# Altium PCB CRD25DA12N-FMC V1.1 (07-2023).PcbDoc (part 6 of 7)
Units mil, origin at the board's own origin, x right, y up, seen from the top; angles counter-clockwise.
Board outline 8000 x 8000 mil, 6 copper layers (Top Layer, Layer 2, Layer 3, Layer 4, Layer 5, Bottom Layer), stack 91 mil thick; 542 components, 315 nets, 1585 pads, 558 vias.
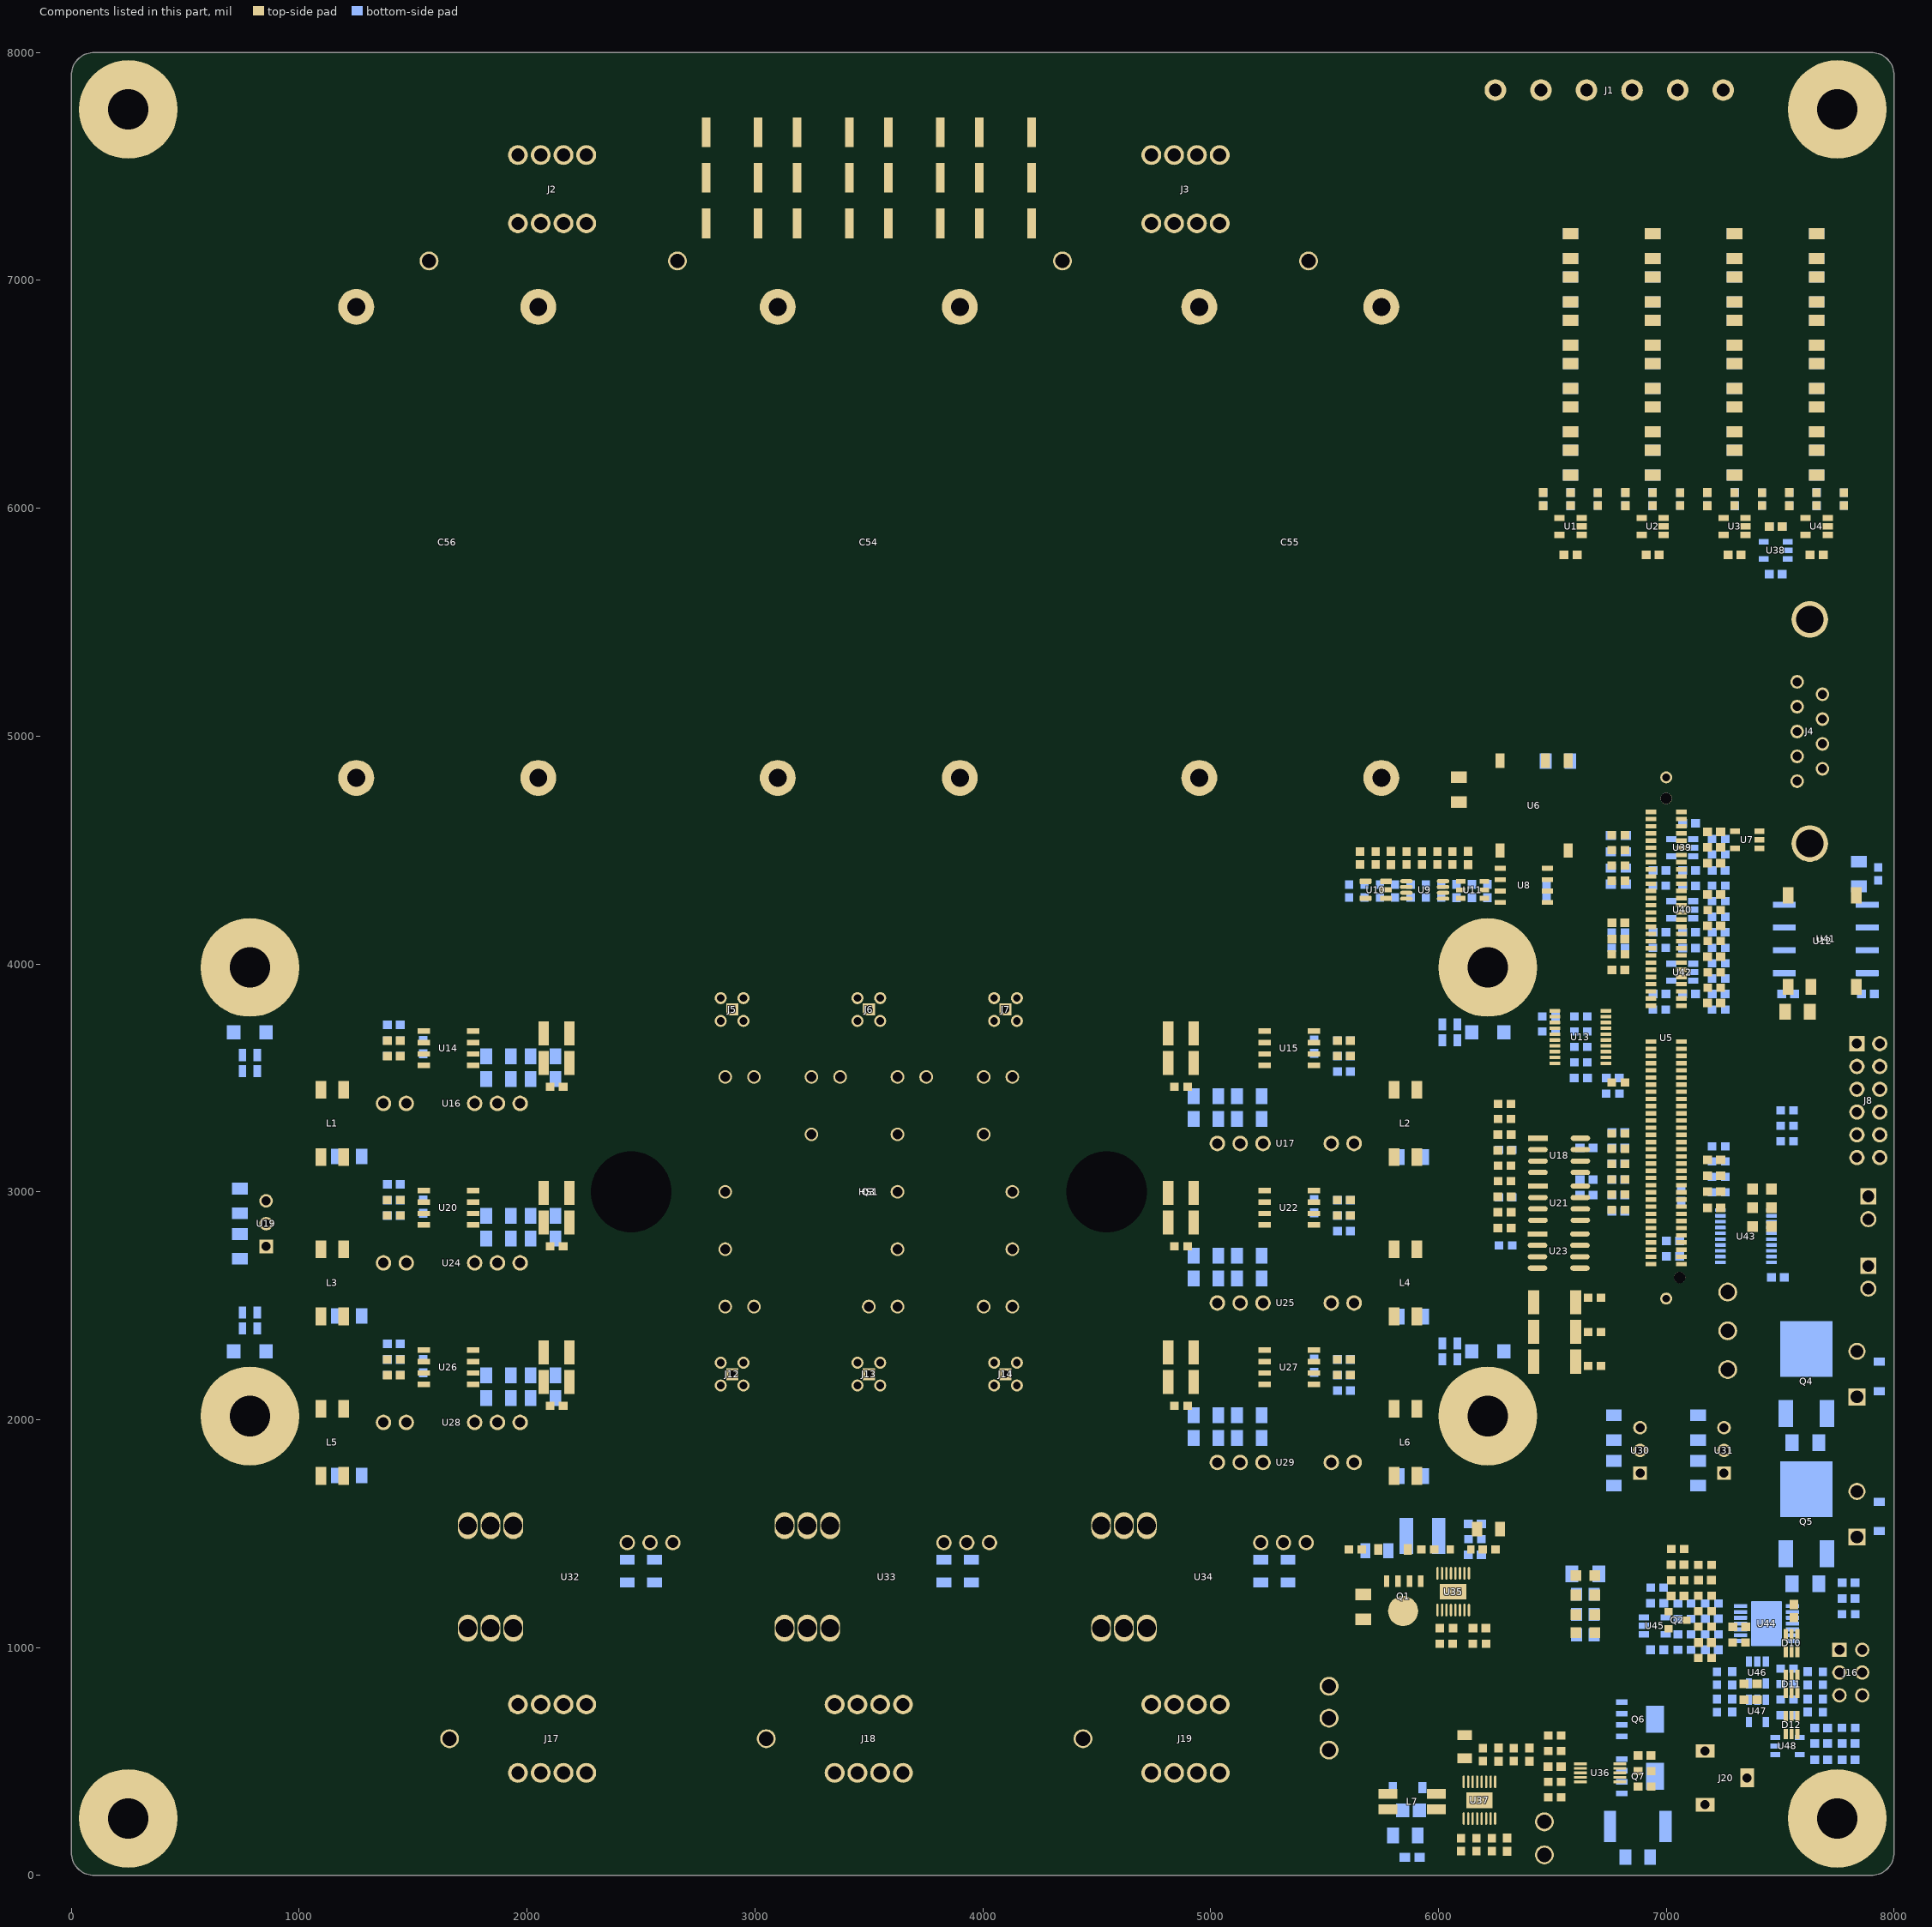
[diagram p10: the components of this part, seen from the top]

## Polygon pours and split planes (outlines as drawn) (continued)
GND on Bottom Layer "GND_L06_P148" (solid, pour order 148): 6825,1941.88 6856.88,1910 6935,1910 6935,1820 6856.88,1820 6825,1788.12 6825,1770 6715,1770 6715,1960 6825,1960
+3.3V on Bottom Layer "+3.3V_L06_P146" (solid, pour order 146): 6803.12,1970 6835,1938.12 6835,1920 6935,1920 6935,2065 6715,2065 6715,1970
GND on Bottom Layer "GND_L06_P145" (solid, pour order 145): 7470,1495 7470,1330 7625,1330 7625,1495
DC- on Layer 5 "DC-_L05_P275" (solid, pour order 275): 1084,3924 2231,3924 2320,3835 2320,2930 4565,2930 5365,3730 5365,4050 5455,4140 5772.5,4137.5 6238,4603 6238,7740 758,7740 758,4250
GND on Layer 5 "GND_L05_P266" (solid, pour order 266): 54 vertices, not listed, extent 2385,50 7950,6175
S4 on Layer 5 "S4_L05_P090" (solid, pour order 90): 4745,2370 5265,2370 5265,1775 4745,1775
S6 on Layer 5 "S6_L05_P091" (solid, pour order 91): 4745,3070 5265,3070 5265,2475 4745,2475
S5 on Layer 5 "S5_L05_P092" (solid, pour order 92): 4745,3770 5265,3770 5265,3175 4745,3175
S1 on Layer 5 "S1_L05_P033" (solid, pour order 33): 1735,3080 2245,3080 2245,2625 1735,2625
S2 on Layer 5 "S2_L05_P341" (solid, pour order 341): 1735,2380 2245,2380 2245,1925 1735,1925
S3 on Layer 5 "S3_L05_P342" (solid, pour order 342): 1735,3780 2245,3780 2245,3325 1735,3325
GND on Layer 5 "GND_L05_P304" (solid, pour order 304): 1395,1850 1470,1850 1470,1925 1575,1925 1575,3725 490,3725 490,1680 1395,1680
U_OUT on Layer 5 "U_OUT_L05_P169" (solid, pour order 169): 1545,1620 1545,340 2455,340 2455,1015 2165,1305 2165,1620
V_OUT on Layer 5 "V_OUT_L05_P168" (solid, pour order 168): 2935,1620 2935,340 3845,340 3845,1015 3555,1305 3555,1620
W_OUT on Layer 5 "W_OUT_L05_P016" (solid, pour order 16): 4325,1620 4325,340 5235,340 5235,1015 4945,1305 4945,1620
GND_ISO on Layer 5 "GND_ISO_L05_P138" (solid, pour order 138): 7725,4445 7725,4365 7810,4365 7810,3845 7950,3845 7950,5595 7540,5595 7540,4445
GND_NTC on Layer 5 "GND_NTC_L05_P263" (solid, pour order 263): 6055,4575 6000,4575 6000,4520 5585,4520 5585,4235 6295,4235 6295,4925 6055,4925
+12V on Top Layer "+12V_L01_P193" (solid, pour order 193): 5880,3795 5880,3940 5805,4015 5580,4015 5205,4390 1545,4390 790,3635 790,3360 960,3360 965,3365 965,3615 1690,4340 5115,4340 5660,3795
G3 on Top Layer "G3_L01_P128" (solid, pour order 128): 18 vertices, not listed, extent 2130,3450 3405,4070
G1 on Top Layer "G1_L01_P061" (solid, pour order 61): 2150,2810 2150,2750 2170,2750 2170,2810 2210,2810 2210,3075 2585,3450 3008.94,3450 3008.94,3560 2520,3560 2130,3170 2130,2810
G2 on Top Layer "G2_L01_P060" (solid, pour order 60): 2150,2110 2150,2050 2170,2050 2170,2110 2210,2110 2210,2210 2445,2445 3045,2445 3045,2555 2400,2555 2195,2350 2130,2350 2130,2110
G6 on Top Layer "G6_L01_P059" (solid, pour order 59): 4775,3060 4775,2800 4530,2555 3955,2555 3955,2445 4615,2445 4870,2700 4870,3060
G5 on Top Layer "G5_L01_P057" (solid, pour order 57): 4735,3665 4789.19,3610.81 4790,3610.81 4790,3440 4870,3440 4870,3754.99 3780.01,3755.01 3705,3680 3705,3515 3755,3465 3795,3465 3795,3600 3860,3665
G4 on Top Layer "G4_L01_P056" (solid, pour order 56): 19 vertices, not listed, extent 3605,1940 4870,2535
+15V on Top Layer "+15V_L01_P235" (solid, pour order 235): 5600,1175 5600,1045 5940,1045 5940,1240 5730,1240 5730,1175
NetD4_2 on Top Layer "NETD4_2_L01_P227" (solid, pour order 227): 5900,1400 5901.49,1400 6015,1400 6015,1120 5950,1120 5950,1360 5830,1360 5830,1475 5900,1475
NetC182_2 on Top Layer "NETC182_2_L01_P224" (solid, pour order 224): 17 vertices, not listed, extent 5840,175 6155,450
GND on Top Layer "GND_L01_P434" (solid, pour order 434): 6530,5000 6530,4825 6638.38,4825 6638.38,5000
+5V_NTC on Top Layer "+5V_NTC_L01_P213" (solid, pour order 213): 6149.83,4525 6200.06,4474.77 6200,4474.77 6200,4445 6295,4445 6295,4760 6055,4760 6055,4675 6055,4525
GND_NTC on Top Layer "GND_NTC_L01_P215" (solid, pour order 215): 6210,4925 6055,4925 6055,4770 6295,4770 6295,4925
GND on Top Layer "GND_L01_P431" (solid, pour order 431): 5715,3305 5715,3555 5850,3555 5850,3305
+12V on Top Layer "+12V_L01_P430" (solid, pour order 430): 5945,3305 5945,3555 5860,3555 5860,3305
NetC105_2 on Top Layer "NETC105_2_L01_P429" (solid, pour order 429): 5850,3065 5480,3065 5480,3295 5850,3295
NetC105_1 on Top Layer "NETC105_1_L01_P428" (solid, pour order 428): 5945,3295 5945,3065 5860,3065 5860,3295
GND on Top Layer "GND_L01_P427" (solid, pour order 427): 5715,2605 5715,2855 5850,2855 5850,2605
+12V on Top Layer "+12V_L01_P426" (solid, pour order 426): 5945,2605 5945,2855 5860,2855 5860,2605
NetC135_2 on Top Layer "NETC135_2_L01_P425" (solid, pour order 425): 5850,2365 5480,2365 5480,2595 5850,2595
NetC135_1 on Top Layer "NETC135_1_L01_P424" (solid, pour order 424): 5945,2595 5945,2365 5860,2365 5860,2595
+12V on Top Layer "+12V_L01_P379" (solid, pour order 379): 1235,1945 1235,2150 1145,2150 1145,1945
NetC157_1 on Top Layer "NETC157_1_L01_P376" (solid, pour order 376): 1195,1935 1195,1937.5 1245,1987.5 1245,2040 1525,2040 1525,1925 1455,1925 1450,1925 1395,1870 1395,1680 1145,1680 1145,1935
NetC156_1 on Top Layer "NETC156_1_L01_P102" (solid, pour order 102): 5945,1895 5945,1665 5860,1665 5860,1895
NetC156_2 on Top Layer "NETC156_2_L01_P103" (solid, pour order 103): 5850,1665 5480,1665 5480,1895 5850,1895
+12V on Top Layer "+12V_L01_P178" (solid, pour order 178): 5945,1905 5945,2155 5860,2155 5860,1905
GND on Top Layer "GND_L01_P184" (solid, pour order 184): 5715,1905 5715,2155 5850,2155 5850,1905
G5L on Top Layer "G5L_L01_P423" (solid, pour order 423): 5265,3595 5265,3620 4900,3620 4900,3510 5100,3510 5185,3595
G5H on Top Layer "G5H_L01_P422" (solid, pour order 422): 5265,3665 5265,3640 4900,3640 4900,3750 5100,3750 5185,3665
+15V_W_HS on Top Layer "-3V_U_LS_TOP" (solid, pour order 421): 5265,3770 5265,3675 5190,3675 5145,3720 5145,3770
-3V_W_HS on Top Layer "+15V_U_LS_TOP" (solid, pour order 420): 5265,3585 5265,3410 5165,3410 5165,3555 5195,3585
G6L on Top Layer "G6L_L01_P419" (solid, pour order 419): 5265,2895 5265,2920 4900,2920 4900,2810 5100,2810 5185,2895
G6H on Top Layer "G6H_L01_P418" (solid, pour order 418): 5265,2965 5265,2940 4900,2940 4900,3050 5100,3050 5185,2965
+15V_W_LS on Top Layer "-3V_U_LS_TOP" (solid, pour order 417): 5265,3070 5265,2975 5190,2975 5145,3020 5145,3070
-3V_W_LS on Top Layer "+15V_U_LS_TOP" (solid, pour order 416): 5265,2885 5265,2710 5165,2710 5165,2855 5195,2885
G4L on Top Layer "G4L_L01_P409" (solid, pour order 409): 5265,2195 5265,2220 4900,2220 4900,2110 5100,2110 5185,2195
G4H on Top Layer "G4H_L01_P408" (solid, pour order 408): 5265,2265 5265,2240 4900,2240 4900,2350 5100,2350 5185,2265
G2H on Top Layer "G2H_L01_P407" (solid, pour order 407): 1735,2195 1735,2220 2100,2220 2100,2110 1900,2110 1815,2195
-3V_U_LS on Top Layer "-3V_U_LS_TOP" (solid, pour order 406): 1735,2370 1735,2275 1810,2275 1855,2320 1855,2370
+15V_U_LS on Top Layer "+15V_U_LS_TOP" (solid, pour order 405): 1860,2035 1915,1980 1915,1925 2015,1925 2015,2095 1900,2095 1810,2185 1735,2185 1735,2035
G2L on Top Layer "G2L_L01_P404" (solid, pour order 404): 1735,2265 1735,2240 2100,2240 2100,2350 1900,2350 1815,2265
G3H on Top Layer "G3H_L01_P403" (solid, pour order 403): 1735,3595 1735,3620 2100,3620 2100,3510 1900,3510 1815,3595
-3V_V_HS on Top Layer "-3V_U_LS_TOP" (solid, pour order 402): 1735,3770 1735,3675 1810,3675 1855,3720 1855,3770
+15V_V_HS on Top Layer "+15V_U_LS_TOP" (solid, pour order 401): 1860,3435 1915,3380 1915,3325 2015,3325 2015,3495 1900,3495 1810,3585 1735,3585 1735,3435
G3L on Top Layer "G3L_L01_P400" (solid, pour order 400): 1735,3665 1735,3640 2100,3640 2100,3752.8 1902.8,3752.79 1815,3665
+12V on Top Layer "+12V_L01_P383" (solid, pour order 383): 1235,3345 1235,3550 1145,3550 1145,3345
GND on Top Layer "GND_L01_P382" (solid, pour order 382): 1135,3345 1135,3550 1045,3550 1045,3345
NetC106_2 on Top Layer "NETC106_2_L01_P381" (solid, pour order 381): 1045,3335 1045,3075 1135,3075 1135,3335
NetC106_1 on Top Layer "NETC106_1_L01_P380" (solid, pour order 380): 1195,3335 1195,3337.5 1245,3387.5 1245,3440 1525,3440 1525,3325 1455,3325 1450,3325 1395,3270 1395,3080 1145,3080 1145,3335
GND on Top Layer "GND_L01_P378" (solid, pour order 378): 1135,1945 1135,2150 1045,2150 1045,1945
NetC157_2 on Top Layer "NETC157_2_L01_P377" (solid, pour order 377): 1045,1935 1045,1675 1135,1675 1135,1935
NetC136_1 on Top Layer "NETC136_1_L01_P077" (solid, pour order 77): 1195,2635 1195,2637.5 1245,2687.5 1245,2740 1525,2740 1525,2625 1455,2625 1450,2625 1395,2570 1395,2380 1145,2380 1145,2635
+12V on Top Layer "+12V_L01_P375" (solid, pour order 375): 1235,2645 1235,2850 1145,2850 1145,2645
NetC136_2 on Top Layer "NETC136_2_L01_P078" (solid, pour order 78): 1045,2635 1045,2375 1135,2375 1135,2635
G1H on Top Layer "G1H_L01_P374" (solid, pour order 374): 1735,2895 1735,2920 2100,2920 2100,2810 1900,2810 1815,2895
+15V_U_HS on Top Layer "+15V_U_LS_TOP" (solid, pour order 330): 1860,2735 1915,2680 1915,2625 2015,2625 2015,2795 1900,2795 1810,2885 1735,2885 1735,2735
NetC159_1 on Top Layer "NETC159_1_L01_P233" (solid, pour order 233): 5630,1475 5630,1385 5685,1330 5795,1330 5795,1265 5935,1265 5935,1345 5820,1345 5820,1475
U_OUT on Top Layer "U_OUT_L01_P278" (solid, pour order 278): 1545,1620 1545,340 2455,340 2455,1015 2165,1305 2165,1620
W_OUT on Top Layer "W_OUT_L01_P276" (solid, pour order 276): 4325,1615 4325,340 5235,340 5235,1015 4945,1305 4945,1615
V_OUT on Top Layer "V_OUT_L01_P277" (solid, pour order 277): 2935,1620 2935,340 3845,340 3845,1015 3555,1305 3555,1620
-3V_U_HS on Top Layer "-3V_U_LS_TOP" (solid, pour order 331): 1735,3070 1735,2975 1810,2975 1855,3020 1855,3070
G1L on Top Layer "G1L_L01_P329" (solid, pour order 329): 1735,2965 1735,2940 2100,2940 2100,3050 1900,3050 1815,2965
-3V_V_LS on Top Layer "+15V_U_LS_TOP" (solid, pour order 124): 5265,2185 5265,2010 5165,2010 5165,2155 5195,2185
+15V_V_LS on Top Layer "-3V_U_LS_TOP" (solid, pour order 125): 5265,2370 5265,2275 5190,2275 5145,2320 5145,2370
+5V_ISO on Top Layer "+5V_ISO_L01_P291" (solid, pour order 291): 7795,4405 7795,4250 7920,4250 7920,4405
GND_ISO on Top Layer "GND_ISO_L01_P289" (solid, pour order 289): 7795,3950 7795,3845 7940,3845 7940,3950
GND on Top Layer "GND_L01_P284" (solid, pour order 284): 7575,3950 7575,3740 7465,3740 7465,3950
+3.3V on Top Layer "+3.3V_L01_P283" (solid, pour order 283): 7585,3950 7585,3740 7705,3740 7705,3880 7675,3880 7675,3950
+5V on Top Layer "+5V_L01_P217" (solid, pour order 217): 6410,5000 6410,4825 6520,4825 6520,5000
+12V on Top Layer "+12V_L01_P228" (solid, pour order 228): 6215,1605 5985,1605 5985,1525 6105,1525 6105,1395 6170,1395 6170,1460 6215,1460
GND on Top Layer "GND_L01_P236" (solid, pour order 236): 5600,1300 5600,1185 5720,1185 5720,1300
GND on Top Layer "GND_L01_P231" (solid, pour order 231): 6230,1460 6230,1605 6330,1605 6330,1460
GND on Top Layer "GND_L01_P196" (solid, pour order 196): 1135,2645 1135,2850 1045,2850 1045,2645
NetC182_1 on Top Layer "NETC182_1_L01_P191" (solid, pour order 191): 5880,340 5880,480 6055,480 6055,340
-15V on Top Layer "-15V_L01_P189" (solid, pour order 189): 5830,250 5870,250 5870,330 5680,330 5680,135 5685,135 5830,135
+12V on Top Layer "+12V_L01_P188" (solid, pour order 188): 5705,480 5705,340 5870,340 5870,480
GND on Top Layer "GND_L01_P166" (solid, pour order 166): 6340,2215 6380,2175 6475,2175 6475,2590 6340,2590

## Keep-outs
Top Layer:
  region: 2470,330 2470,370 2400,370 2400,330
  rectangle: 1535,325 1575,395
  region: 3566.21,1635.39 3526.21,1635.39 3526.21,1565.39 3566.21,1565.39
  region: 5250,330 5250,370 5180,370 5180,330
  rectangle: 4315,325 4355,395
  rectangle: 2925,325 2965,395
  region: 3860,330 3860,370 3790,370 3790,330
  region: 2175,1635 2135,1635 2135,1565 2175,1565
  region: 2921.21,1630.39 2921.21,1590.39 2991.21,1590.39 2991.21,1630.39
  region: 4310,1625 4310,1585 4380,1585 4380,1625
  region: 4955,1630 4915,1630 4915,1560 4955,1560
  region: 1530,1630 1530,1590 1600,1590 1600,1630
  rectangle: 2925,325 2965,395
  rectangle: 4315,325 4355,395
  region: 3860,330 3860,370 3790,370 3790,330
  region: 5250,330 5250,370 5180,370 5180,330
  region: 2470,330 2470,370 2400,370 2400,330
  rectangle: 1535,325 1575,395
  lines w10: 785.01,3404.2 ccw(c835,3405) 835.8,3355.01 ; 920.8,3355.01 ccw(c920,3405) 969.99,3405.8 ; 1039.2,1989.19 ccw(c1089.2,1989.99) 1090,1940 ; 1039.2,2689.19 ccw(c1089.2,2689.99) 1090,2640 ; 1039.2,3389.19 ccw(c1089.2,3389.99) 1090,3340 ; 1040,1720 ccw(c1090,1720) 1090,1670 ccw(c1090,1720) 1140,1720 ; 1040,1890 cw(c1090,1890) 1090,1940 ; 1040.01,2104.2 cw(c1090,2105) 1089.2,2154.99 cw(c1090,2105) 1139.99,2105.8 ; 1040,2420 ccw(c1090,2420) 1090,2370 ccw(c1090,2420) 1140,2420 ; 1040,2590 cw(c1090,2590) 1090,2640 ; 1040.01,2804.2 cw(c1090,2805) 1089.2,2854.99 cw(c1090,2805) 1139.99,2805.8 ; 1040,3120 ccw(c1090,3120) 1090,3070 ccw(c1090,3120) 1140,3120 ; 1040,3290 cw(c1090,3290) 1090,3340 ; 1040.01,3504.2 cw(c1090,3505) 1089.2,3554.99 cw(c1090,3505) 1139.99,3505.8 ; 1090.8,1940.01 ccw(c1090,1990) 1139.99,1990.8 ; 1090.8,2640.01 ccw(c1090,2690) 1139.99,2690.8 ; 1090.8,3340.01 ccw(c1090,3390) 1139.99,3390.8 ; 1139.2,1989.19 ccw(c1189.2,1989.99) 1190,1940 ; 1139.2,2689.19 ccw(c1189.2,2689.99) 1190,2640 ; 1139.2,3389.19 ccw(c1189.2,3389.99) 1190,3340 ; 1140,1725 ccw(c1190,1725) 1190,1675 ; 1140.01,2104.2 cw(c1190,2105) 1189.2,2154.99 ; 1140,2425 ccw(c1190,2425) 1190,2375 ; 1140.01,2804.2 cw(c1190,2805) 1189.2,2854.99 ; 1140,3125 ccw(c1190,3125) 1190,3075 ; 1140.01,3504.2 cw(c1190,3505) 1189.2,3554.99 ; 1190,2155 cw(c1190,2105) 1240,2105 ; 1190,2855 cw(c1190,2805) 1240,2805 ; 1190,3555 cw(c1190,3505) 1240,3505 ; 1239.2,1994.99 cw(c1289.2,1994.99) 1289.2,2044.99 ; 1239.2,2694.99 cw(c1289.2,2694.99) 1289.2,2744.99 ; 1239.2,3394.99 cw(c1289.2,3394.99) 1289.2,3444.99 ; 1240,1990 cw(c1190,1990) 1190,1940 ; 1240,2690 cw(c1190,2690) 1190,2640 ; 1240,3390 cw(c1190,3390) 1190,3340 ; 1350,1675 ccw(c1350,1725) 1400,1725 ; 1350,2375 ccw(c1350,2425) 1400,2425 ; 1350,3075 ccw(c1350,3125) 1400,3125 ; 1400.01,1869.2 cw(c1450,1870) 1449.2,1919.99 ; 1400.01,2569.2 cw(c1450,2570) 1449.2,2619.99 ; 1400.01,3269.2 cw(c1450,3270) 1449.2,3319.99 ; 1479.2,2044.99 cw(c1480,1995) 1529.99,1995.8 ; 1479.2,2744.99 cw(c1480,2695) 1529.99,2695.8 ; 1479.2,3444.99 cw(c1480,3395) 1529.99,3395.8 ; 1480.8,1920.01 ccw(c1480,1970) 1529.99,1970.8 ; 1480.8,2620.01 ccw(c1480,2670) 1529.99,2670.8 ; 1480.8,3320.01 ccw(c1480,3370) 1529.99,3370.8 ; 1540.02,1477.41 cw(c1690,1475) 1692.41,1624.98 ; 1730,2080 ccw(c1780,2080) 1780,2030 ; 1730,2780 ccw(c1780,2780) 1780,2730 ; 1730,3480 ccw(c1780,3480) 1780,3430 ; 1730.8,2325.01 cw(c1780.8,2325.01) 1780.8,2375.01 ; 1730.8,3025.01 cw(c1780.8,3025.01) 1780.8,3075.01 ; 1730.8,3725.01 cw(c1780.8,3725.01) 1780.8,3775.01 ; 1810,2375 cw(c1810,2325) 1860,2325 ; 1810,3075 cw(c1810,3025) 1860,3025 ; 1810,3775 cw(c1810,3725) 1860,3725 ; 1860,2030 cw(c1860,1980) 1910,1980 ; 1860,2730 cw(c1860,2680) 1910,2680 ; 1860,3430 cw(c1860,3380) 1910,3380 ; 1910,1970 ccw(c1960,1970) 1960,1920 ; 1910,2670 ccw(c1960,2670) 1960,2620 ; 1910,3370 ccw(c1960,3370) 1960,3320 ; 1970,1920 ccw(c1970,1970) 2020,1970 ; 1970,2100 cw(c1970,2050) 2020,2050 ; 1970,2620 ccw(c1970,2670) 2020,2670 ; 1970,2800 cw(c1970,2750) 2020,2750 ; 1970,3320 ccw(c1970,3370) 2020,3370 ; 1970,3500 cw(c1970,3450) 2020,3450 ; 2022.41,1624.98 cw(c2020,1475) 2169.98,1472.59 ; 2931.23,1477.81 cw(c3081.21,1475.39) 3083.62,1625.37 ; 2965.8,3445.01 ccw(c2965,3495) 3014.99,3495.8 ; 2999.2,2559.99 cw(c3000,2510) 3049.99,2510.8 ; 3000.8,2440.01 ccw(c3000,2490) 3049.99,2490.8 ; 3250.01,3499.2 ccw(c3300,3500) 3300.8,3450.01 ; 3360.8,3450.01 ccw(c3360,3500) 3409.99,3500.8 ; 3413.62,1625.37 cw(c3411.21,1475.39) 3561.19,1472.98 ; 3600.01,2489.2 cw(c3650,2490) 3649.2,2539.99 ; 3669.2,2539.99 cw(c3670,2490) 3719.99,2490.8 ; 3720.01,2054.2 ccw(c3770,2055) 3770.8,2005.01 ; 3750.8,3460.01 ccw(c3750,3510) 3799.99,3510.8 ; 3950.01,2489.2 ccw(c4000,2490) 4000.8,2440.01 ; 3950.01,2509.2 cw(c4000,2510) 3999.2,2559.99 ; 4320.02,1472.41 cw(c4470,1470) 4472.41,1619.98 ; 4735,3660 cw(c4735.8,3610.01) 4785.8,3610.81 ; 4770.01,3015.8 cw(c4820,3015) 4820.8,3064.99 ; 4770.81,2309.2 cw(c4820.8,2310.01) 4820,2360 ; 4802.41,1619.98 cw(c4800,1470) 4949.98,1467.59 ; 5140,2325 cw(c5190,2325) 5190,2375 ; 5140,3025 cw(c5190,3025) 5190,3075 ; 5140,3725 cw(c5190,3725) 5190,3775 ; 5159.2,2054.19 ccw(c5209.2,2054.99) 5210,2005 ; 5159.2,2754.19 ccw(c5209.2,2754.99) 5210,2705 ; 5159.2,3454.19 ccw(c5209.2,3454.99) 5210,3405 ; 5219.2,2375.01 cw(c5219.2,2325.01) 5269.2,2325.01 ; 5219.2,3075.01 cw(c5219.2,3025.01) 5269.2,3025.01 ; 5219.2,3775.01 cw(c5219.2,3725.01) 5269.2,3725.01 ; 5220.81,2004.2 ccw(c5220.01,2054.2) 5270,2055 ; 5220.81,2704.2 ccw(c5220.01,2754.2) 5270,2755 ; 5220.81,3404.2 ccw(c5220.01,3454.2) 5270,3455 ; 5475,1710 ccw(c5525,1710) 5525,1660 ; 5475,2410 ccw(c5525,2410) 5525,2360 ; 5475,3110 ccw(c5525,3110) 5525,3060 ; 5475.81,1849.2 cw(c5525.8,1850.01) 5525,1900 ; 5475.81,2549.2 cw(c5525.8,2550.01) 5525,2600 ; 5475.81,3249.2 cw(c5525.8,3250.01) 5525,3300 ; 5675,180 ccw(c5725,180) 5725,130 ; 5710,1950 ccw(c5760,1950) 5760,1900 ; 5710,2110 cw(c5759.99,2110.8) 5759.19,2160.8 ; 5710,2650 ccw(c5760,2650) 5760,2600 ; 5710,2810 cw(c5759.99,2810.8) 5759.19,2860.8 ; 5710,3350 ccw(c5760,3350) 5760,3300 ; 5710,3510 cw(c5759.99,3510.8) 5759.19,3560.8 ; 5785,130 ccw(c5785,180) 5835,180 ; 5805,1660 ccw(c5805,1710) 5855,1710 ccw(c5905,1710) 5905,1660 ; 5805,2160 cw(c5805,2110) 5855,2110 cw(c5905,2110) 5905,2160 ; 5805,2360 ccw(c5805,2410) 5855,2410 ccw(c5905,2410) 5905,2360 ; 5805,2860 cw(c5805,2810) 5855,2810 cw(c5905,2810) 5905,2860 ; 5805,3060 ccw(c5805,3110) 5855,3110 ccw(c5905,3110) 5905,3060 ; 5805,3560 cw(c5805,3510) 5855,3510 cw(c5905,3510) 5905,3560 ; 5825,330 cw(c5825,280) 5875,280 cw(c5925,280) 5925,330 ; 5825,335 ccw(c5825,385) 5875,385 ccw(c5925,385) 5925,335 ; 5825,485 cw(c5825,435) 5875,435 cw(c5925,435) 5925,485 ; 5835.8,3790.01 ccw(c5835,3840) 5884.99,3840.8 ; 5900,1660 ccw(c5900,1710) 5950,1710 ; 5900,2160 cw(c5900,2110) 5950,2110 ; 5900,2360 ccw(c5900,2410) 5950,2410 ; 5900,2860 cw(c5900,2810) 5950,2810 ; 5900,3060 ccw(c5900,3110) 5950,3110 ; 5900,3560 cw(c5900,3510) 5950,3510 ; 5950,1850 ccw(c5900,1850) 5900,1900 ccw(c5900,1950) 5950,1950 ; 5950,2550 ccw(c5900,2550) 5900,2600 ccw(c5900,2650) 5950,2650 ; 5950,3250 ccw(c5900,3250) 5900,3300 ccw(c5900,3350) 5950,3350 ; 6010,485 cw(c6010,435) 6060,435 ; 6015,330 ccw(c6015,380) 6065,380 ; 6050,4570 ccw(c6100,4570) 6100,4520 ; 6050,4715 cw(c6100,4715) 6100,4765 cw(c6100,4815) 6050,4815 ; 6050,4880 cw(c6100,4880) 6100,4930 ; 6065,430 cw(c6090,430) 6090,455 ; 6145,4520 cw(c6145,4470) 6195,4470 ; 6195.02,4472.9 ccw(c6242,4490) 6242,4440 ; 6250,4440 ccw(c6250,4490) 6300,4490 ; 6250,4930 cw(c6250,4880) 6300,4880 ; 6300,4715 ccw(c6250,4715) 6250,4765 ccw(c6250,4815) 6300,4815 ; 6335,2220 ccw(c6385,2220) 6385,2170 ; 6335,2545 cw(c6385,2545) 6385,2595 ; 6405,4870 ccw(c6455,4870) 6455,4820 ; 6405,4955 cw(c6455,4955) 6455,5005 ; 6430,2170 ccw(c6430,2220) 6480,2220 ; 6430,2595 cw(c6430,2545) 6480,2545 ; 6475,4820 ccw(c6475,4870) 6525,4870 ccw(c6575,4870) 6575,4820 ; 6475,5005 cw(c6475,4955) 6525,4955 cw(c6575,4955) 6575,5005 ; 6595,4820 ccw(c6595,4870) 6645,4870 ; 6595,5005 cw(c6595,4955) 6645,4955 ; 1090,1940 cw(c1090,1890) 1140,1890 cw(c1190,1890) 1190,1940 ; 1090,2640 cw(c1090,2590) 1140,2590 cw(c1190,2590) 1190,2640 ; 1090,3340 cw(c1090,3290) 1140,3290 cw(c1190,3290) 1190,3340 ; 1540.02,487.41 ccw(c1690,485) 1687.59,335.02 cw(c1690,485) 1540.02,487.41 ; 2307.59,335.02 ccw(c2310,485) 2459.98,482.59 cw(c2310,485) 2307.59,335.02 ; 2930.02,487.41 ccw(c3080,485) 3077.59,335.02 cw(c3080,485) 2930.02,487.41 ; 3697.59,335.02 ccw(c3700,485) 3849.98,482.59 cw(c3700,485) 3697.59,335.02 ; 4320.02,487.41 ccw(c4470,485) 4467.59,335.02 cw(c4470,485) 4320.02,487.41 ; 5087.59,335.02 ccw(c5090,485) 5239.98,482.59 cw(c5090,485) 5087.59,335.02 ; 5805,1900 ccw(c5805,1950) 5855,1950 ccw(c5905,1950) 5905,1900 ccw(c5905,1850) 5855,1850 ccw(c5805,1850) 5805,1900 ; 5805,2600 cw(c5805,2550) 5855,2550 cw(c5905,2550) 5905,2600 cw(c5905,2650) 5855,2650 cw(c5805,2650) 5805,2600 ; 5805,3300 cw(c5805,3250) 5855,3250 cw(c5905,3250) 5905,3300 cw(c5905,3350) 5855,3350 cw(c5805,3350) 5805,3300
Layer 2:
  region: 1425.76,1895.43 1425.76,1855.43 1495.76,1855.43 1495.76,1895.43
  region: 4955,1630 4915,1630 4915,1560 4955,1560
  region: 4310,1625 4310,1585 4380,1585 4380,1625
  region: 3565,1635 3525,1635 3525,1565 3565,1565
  region: 2920,1615 2920,1575 2990,1575 2990,1615
  region: 2175,1620 2135,1620 2135,1550 2175,1550
  region: 1530,1630 1530,1590 1600,1590 1600,1630
  region: 5250,330 5250,370 5180,370 5180,330
  region: 5250,330 5250,370 5180,370 5180,330
  rectangle: 4315,325 4355,395
  rectangle: 4315,325 4355,395
  region: 3860,330 3860,370 3790,370 3790,330
  region: 3860,330 3860,370 3790,370 3790,330
  rectangle: 2925,325 2965,395
  rectangle: 2925,325 2965,395
  region: 2470,330 2470,370 2400,370 2400,330
  region: 2470,330 2470,370 2400,370 2400,330
  rectangle: 1535,325 1575,395
  rectangle: 1535,325 1575,395
  rectangle: 5305,260 5345,330
  rectangle: 4195,255 4235,325
  rectangle: 5317.18,1103.22 5357.18,1173.22
  rectangle: 5365,1545 5405,1615
  rectangle: 7455.41,5521.71 7515,5665
  rectangle: 7455.79,4364.18 7515.39,4507.46
  rectangle: 7734.19,3725 7793.78,3868.29
  rectangle: 7724.19,4275 7783.78,4418.29
  rectangle: 3920,260 3960,330
  rectangle: 3931.38,1103.21 3971.38,1173.21
  rectangle: 2800,260 2840,330
  rectangle: 2541.38,1103.21 2581.38,1173.21
  rectangle: 7524,30 7654,255
  rectangle: 7754,331.5 7970,476.5
  rectangle: 7825,40 7960,165
  lines w10: 485,1750 ccw(c560,1750) 560,1675 ; 485.01,4358.79 cw(c560,4360) 558.79,4434.99 ; 1325,1675 ccw(c1325,1750) 1400,1750 ; 1400.01,1843.79 cw(c1475,1845) 1473.79,1919.99 ; 1505,1920 ccw(c1503.79,1994.99) 1578.78,1996.2 ; 1540,1475 cw(c1690,1475) 1690,1625 ; 1730,2167 ccw(c1780,2167) 1762.9,2120.02 ; 1730,2265 cw(c1780,2265) 1780,2315 1805,2315 ; 1730,2867 ccw(c1780,2867) 1762.9,2820.02 ; 1730,2965 cw(c1780,2965) 1780,3015 1805,3015 ; 1730,3567 ccw(c1780,3567) 1762.9,3520.02 ; 1730,3665 cw(c1780,3665) 1780,3715 1805,3715 ; 1781.32,2069.24 ccw(c1828.3,2052.14) 1790,2020 ; 1781.32,2769.24 ccw(c1828.3,2752.14) 1790,2720 ; 1781.32,3469.24 ccw(c1828.3,3452.14) 1790,3420 ; 1805,1970 ccw(c1854.99,1970.8) 1855.8,1920.81 ; 1805,2670 ccw(c1854.99,2670.8) 1855.8,2620.81 ; 1805,3370 ccw(c1854.99,3370.8) 1855.8,3320.81 ; 1849,2335 cw(c1899,2335) 1899,2385 ; 1849,3035 cw(c1899,3035) 1899,3085 ; 1849,3735 cw(c1899,3735) 1899,3785 ; 2020,1625 cw(c2020,1475) 2170,1475 ; 2035,3085 ccw(c2035,3135) 2085,3135 ; 2140.8,1920.01 ccw(c2140,1970) 2189.99,1970.8 ; 2210.81,2619.2 ccw(c2210.01,2669.2) 2260,2670 ; 2375.01,1443.79 cw(c2450,1445) 2448.79,1519.99 ; 2544.2,1184.99 cw(c2545,1135) 2594.99,1135.8 ; 2595.01,118.79 ccw(c2670,120) 2671.21,45.01 ; 2703.79,1519.99 cw(c2705,1445) 2779.99,1446.21 ; 2764.2,2409.99 cw(c2765,2360) 2814.99,2360.8 ; 2765.8,3595.01 ccw(c2765,3645) 2814.99,3645.8 ; 2780.01,313.79 ccw(c2855,315) 2856.21,240.01 ; 2815.01,2169.2 ccw(c2865,2170) 2865.8,2120.01 ; 2815.01,3829.2 cw(c2865,3830) 2864.2,3879.99 ; 2930,1475 cw(c3080,1475) 3080,1625 ; 2934.2,3879.99 cw(c2935,3830) 2984.99,3830.8 ; 2935.8,2120.01 ccw(c2935,2170) 2984.99,2170.8 ; 2985.01,2359.2 cw(c3035,2360) 3034.2,2409.99 ; 2985.01,3644.2 ccw(c3035,3645) 3035.8,3595.01 ; 3029.2,2589.99 cw(c3030,2540) 3079.99,2540.8 ; 3029.2,3594.99 cw(c3030,3545) 3079.99,3545.8 ; 3030.8,2410.01 ccw(c3030,2460) 3079.99,2460.8 ; 3030.8,3415.01 ccw(c3030,3465) 3079.99,3465.8 ; 3210.01,3464.2 ccw(c3260,3465) 3260.8,3415.01 ; 3390.26,3416.67 ccw(c3389.46,3466.66) 3439.45,3467.47 ; 3410,1625 cw(c3410,1475) 3560,1475 ; 3420.01,2539.2 cw(c3470,2540) 3469.2,2589.99 ; 3440.01,3669.2 cw(c3490,3670) 3489.2,3719.99 ; 3540.01,3484.2 ccw(c3590,3485) 3590.8,3435.01 ; 3694.2,2589.99 cw(c3695,2540) 3744.99,2540.8 ; 3744.2,2079.19 ccw(c3794.2,2079.99) 3795,2030 ; 3765.01,1443.79 cw(c3840,1445) 3838.79,1519.99 ; 3775.8,3435.01 ccw(c3775,3485) 3824.99,3485.8 ; 3911.21,240.01 ccw(c3910,315) 3984.99,316.21 ; 3920.01,2459.2 ccw(c3970,2460) 3970.8,2410.01 ; 3920.01,2539.2 cw(c3970,2540) 3969.2,2589.99 ; 3934.2,1184.99 cw(c3935,1135) 3984.99,1135.8 ; 3964.2,2409.99 cw(c3965,2360) 4014.99,2360.8 ; 3965.01,3484.2 cw(c4015,3485) 4014.2,3534.99 ; 3965.01,3489.2 ccw(c4015,3490) 4015.8,3440.01 ; 4005.4,3830 ccw(c4005,3855) 4030,3855.4 ; 4015.01,2164.2 ccw(c4065,2165) 4065.8,2115.01 ; 4093.79,1519.99 cw(c4095,1445) 4169.99,1446.21 ; 4135.8,2115.01 ccw(c4135,2165) 4184.99,2165.8 ; 4170.01,313.79 ccw(c4245,315) 4246.21,240.01 ; 4174.6,3834.59 ccw(c4199.6,3835) 4200,3810 ; 4185.01,2359.2 cw(c4235,2360) 4234.2,2409.99 ; 4320,1470 cw(c4470,1470) 4470,1620 ; 4690,3640 cw(c4690.8,3590.01) 4740.8,3590.81 ; 4739.2,2325.81 cw(c4789.2,2325.01) 4790,2375 ; 4739.2,3025.81 cw(c4789.2,3025.01) 4790,3075 ; 4740.81,1820.8 ccw(c4790.8,1819.99) 4790,1770 ; 4740.81,3220.8 ccw(c4790.8,3219.99) 4790,3170 ; 4800,1620 cw(c4800,1470) 4950,1470 ; 5155.01,1443.79 cw(c5230,1445) 5228.79,1519.99 ; 5174.2,3809.99 cw(c5175,3760) 5224.99,3760.8 ; 5220,1770 ccw(c5220.8,1819.99) 5270.8,1819.19 ; 5220,2375 cw(c5219.2,2325.01) 5269.19,2324.2 ; 5220,2470 ccw(c5220.8,2519.99) 5270.8,2519.19 ; 5220,3075 cw(c5219.2,3025.01) 5269.19,3024.2 ; 5220,3170 ccw(c5220.8,3219.99) 5270.8,3219.19 ; 5296.21,240.01 ccw(c5295,315) 5369.99,316.21 ; 5320,1185 cw(c5320.8,1135.01) 5370.8,1135.81 ; 5346.21,1520.01 ccw(c5345,1595) 5419.99,1596.21 ; 5580.01,4280.8 ccw(c5630,4279.99) 5629.2,4230 ; 5580.01,4475.8 cw(c5630,4475) 5630.8,4524.99 ; 5923.79,4104.99 cw(c5925,4030) 5999.99,4031.21 ; 6000,4524.53 ccw(c6000.8,4574.52) 6050.8,4573.71 ; 6050.01,4880.8 cw(c6100,4880) 6100.8,4929.99 ; 6249.2,4230.01 ccw(c6250,4280) 6299.99,4279.2 ; 6250.8,4929.99 cw(c6250,4880) 6299.99,4879.2 ; 6405.01,6103.79 cw(c6480,6105) 6478.79,6179.99 ; 7435.01,4418.79 ccw(c7510,4420) 7511.21,4345.01 ; 7435.01,5608.79 cw(c7510,5610) 7508.79,5684.99 ; 7456.21,45.01 ccw(c7455,120) 7529.99,121.21 ; 7535.01,4513.79 ccw(c7610,4515) 7611.21,4440.01 ; 7535.01,5523.79 cw(c7610,5525) 7608.79,5599.99 ; 7633.8,4343.78 cw(c7635.01,4268.79) 7710,4270 ; 7710.01,3778.79 ccw(c7785,3780) 7786.21,3705.01 ; 7728.79,4439.99 cw(c7730,4365) 7804.99,4366.21 ; 7805.01,3889.2 ccw(c7855,3890) 7855.8,3840.01 ; 7878.79,5599.99 cw(c7880,5525) 7954.99,5526.21 ; 7878.79,6179.99 cw(c7880,6105) 7954.99,6106.21 ; 7881.21,470.01 ccw(c7880,545) 7954.99,546.21 ; 7881.21,5685.01 ccw(c7880,5760) 7954.99,5761.21 ; 7883.79,3704.99 cw(c7885,3630) 7959.99,3631.21 ; 7905.81,3839.2 ccw(c7905.01,3889.2) 7955,3890 ; 1540.02,487.41 ccw(c1690,485) 1687.59,335.02 cw(c1690,485) 1540.02,487.41 ; 2307.59,335.02 ccw(c2310,485) 2459.98,482.59 cw(c2310,485) 2307.59,335.02 ; 2930.02,487.41 ccw(c3080,485) 3077.59,335.02 cw(c3080,485) 2930.02,487.41 ; 3697.59,335.02 ccw(c3700,485) 3849.98,482.59 cw(c3700,485) 3697.59,335.02 ; 4320.02,487.41 ccw(c4470,485) 4467.59,335.02 cw(c4470,485) 4320.02,487.41 ; 5087.59,335.02 ccw(c5090,485) 5239.98,482.59 cw(c5090,485) 5087.59,335.02
Layer 3:
  circle w10: c1960,7550 r200
  circle w10: c1960,7250 r200
  circle w10: c2260,7550 r200
  circle w10: c2260,7250 r200
  circle w10: c4150,3850 r190
  circle w10: c4150,3503.94 r190
  circle w10: c2850,3850 r190
  circle w10: c2850,3503.94 r190
  circle w10: c6065,7280 r192
  region: 2175,1635 2135,1635 2135,1565 2175,1565
  region: 1530,1630 1530,1590 1600,1590 1600,1630
  rectangle: 1780,3085 2345,3295
  region: 1130,4025 1070,4025 1070,3810 1130,3810
  region: 2289.21,6875 2289.21,7180 2256.79,7180 2256.79,6875
  region: 1843.21,6875 1843.21,7180 1810.79,7180 1810.79,6875
  region: 1445.61,7242.78 1171.71,7108.6 1221.38,7007.22 1495.28,7141.4
  region: 1601.27,6999.57 1359.3,6813.89 1428.03,6724.33 1670,6910
  rectangle: 3237.88,3061.97 4005,3330
  rectangle: 1755,7262.91 2465,7802.91
  region: 1775,7755 1735,7755 1735,7685 1775,7685
  region: 2440,7750 2440,7710 2510,7710 2510,7750
  rectangle: 1955,7044.79 2260,7077.21
  region: 4710.94,3890.42 4670.94,3890.42 4670.94,3820.42 4710.94,3820.42
  region: 5905,3971 4805,3971 4805,3915 5905,3915
  rectangle: 7724.19,4275 7783.78,4418.29
  rectangle: 5965,1980 6045,2169.89
  rectangle: 5965,2162.86 6219.18,2244.89
  rectangle: 7809.19,3055 7868.78,3128.29
  rectangle: 7455.79,4364.18 7515.39,4507.46
  rectangle: 7734.19,3725 7793.78,3868.29
  region: 1415.31,1894.07 1415.31,1854.07 1485.31,1854.07 1485.31,1894.07
  rectangle: 5317.18,1103.22 5357.18,1173.22
  rectangle: 5305,260 5345,330
  rectangle: 4195,255 4235,325
  rectangle: 3920,260 3960,330
  rectangle: 3931.38,1103.21 3971.38,1173.21
  rectangle: 2541.38,1103.21 2581.38,1173.21
  rectangle: 2800,260 2840,330
  rectangle: 7524,30 7654,255
  rectangle: 7754,331.5 7970,476.5
  region: 5375,3800 5315,3800 5315,3680 5375,3680
  rectangle: 7825,40 7960,165
  region: 3565,1635 3525,1635 3525,1565 3565,1565
  region: 2920,1630 2920,1590 2990,1590 2990,1630
  region: 4310,1625 4310,1585 4380,1585 4380,1625
  region: 4955,1630 4915,1630 4915,1560 4955,1560
  region: 2470,330 2470,370 2400,370 2400,330
  rectangle: 4315,325 4355,395
  rectangle: 2925,325 2965,395
  region: 3860,330 3860,370 3790,370 3790,330
  region: 5250,330 5250,370 5180,370 5180,330
  rectangle: 1535,325 1575,395
  rectangle: 1125,3800 1725,3894.7
  rectangle: 1095,3856 2195,3971
  rectangle: 1625,3460 1725,3808.71
  region: 1000,4255 940,4255 940,4155 1000,4155
  region: 1060,4200 1000,4200 1000,3985 1060,3985
  region: 1110,4115 1050,4115 1050,3900 1110,3900
  region: 980,4275 810,4275 810,4205 980,4205
  region: 875,4325 705,4325 705,4255 875,4255
  region: 730,7740 730,7700 800,7700 800,7740
  region: 4245,3465 4145,3465 4145,3340 4245,3340
  rectangle: 2850,3310.19 4175.51,4045.42
  rectangle: 2656.25,3503.94 4345.42,3875.51
  region: 2786.06,4030.08 2786.06,3930.08 2911.06,3930.08 2911.06,4030.08
  rectangle: 5476.9,4548.76 5571.9,4630.79
  rectangle: 5445,4497.97 5540,4580
  rectangle: 5530,4582.97 5625,4665
  rectangle: 5425,3790 5568.9,4520
  rectangle: 5545,3935 5810,4185
  rectangle: 4720,3790 5435,3970
  region: 4138.94,4000.08 4138.94,3900.08 4263.94,3900.08 4263.94,4000.08
  region: 4088.94,4030.08 4088.94,3930.08 4213.94,3930.08 4213.94,4030.08
  region: 4178.94,3950.08 4178.94,3850.08 4303.94,3850.08 4303.94,3950.08
  region: 2736.06,4000.08 2736.06,3900.08 2861.06,3900.08 2861.06,4000.08
  rectangle: 2705,3380 2805,3505
  rectangle: 2755,3340 2855,3465
  region: 2696.06,3950.08 2696.06,3850.08 2821.06,3850.08 2821.06,3950.08
  rectangle: 2675,3430 2775,3555
  rectangle: 5590,4537.97 6040,4680
  rectangle: 5650,4132.97 6070,4215
  rectangle: 5895,4568.58 6044.8,4925
  rectangle: 5850,4645 5920,4722.03
  rectangle: 2270.5,3225 2345.5,3845
  rectangle: 2165,3855 2240,3960
  region: 2290,3930 2215,3930 2215,3825 2290,3825
  region: 2310,3910 2235,3910 2235,3805 2310,3805
  region: 2270,3950 2195,3950 2195,3845 2270,3845
  region: 2320,3890 2245,3890 2245,3785 2320,3785
  rectangle: 2335,3170 2375,3240
  rectangle: 2275,2870 2340,3122.06
  region: 4732.79,3962.22 4692.79,3962.22 4692.79,3892.22 4732.79,3892.22
  region: 4705,3945 4665,3945 4665,3875 4705,3875
  region: 4650,3890 4610,3890 4610,3820 4650,3820
  rectangle: 4590,3070 4735,3840
  region: 4295,3505 4195,3505 4195,3380 4295,3380
  region: 4325,3555 4225,3555 4225,3430 4325,3430
  region: 4667.79,3917.22 4627.79,3917.22 4627.79,3847.22 4667.79,3847.22
  region: 6250,7095 6210,7095 6210,7025 6250,7025
  rectangle: 6005,7095 6080,7265.38
  rectangle: 5905,7165 5980,7335.38
  rectangle: 5945,7125 6020,7295.38
  rectangle: 6065,7082.58 6250,7755
  rectangle: 5867.58,7280 6120,7755
  region: 5875,7755 5835,7755 5835,7685 5875,7685
  rectangle: 6190,5050 6260,5127.03
  rectangle: 5997.36,4986.83 6400,5063.86
  rectangle: 5925,4930 6345,5007.03
  rectangle: 6060,4933.58 6400,5085
  lines w10: 433.64,3984.25 cw(c783.46,3984.25) 1133.29,3984.25 ; 485,1750 ccw(c560,1750) 560,1675 ; 485.01,3653.79 cw(c560,3655) 558.79,3729.99 ; 755.02,4450.01 ccw(c880,4448) 877.99,4323.02 ; 755.02,7597.41 cw(c905,7595) 907.41,7744.98 ; 1122.85,4063.45 ccw(c1245,4090) 1242.99,3965.02 ; 1325,1675 ccw(c1325,1750) 1400,1750 ; 1400,1843.79 cw(c1474.99,1845) 1473.78,1919.99 ; 1502.78,3729.23 cw(c1503.99,3654.24) 1578.98,3655.45 ; 1505.19,1919.25 ccw(c1503.99,1994.24) 1578.98,1995.45 ; 1540.02,487.41 ccw(c1690,485) 1687.59,335.02 ; 1540.02,1477.41 cw(c1690,1475) 1692.41,1624.98 ; 1614.41,7744.98 cw(c1612,7595) 1761.98,7592.59 ; 1730,2071.98 ccw(c1780,2071.98) 1762.9,2025 ; 1730,2265 cw(c1780,2265) 1780,2315 1805,2315 ; 1730,2771.98 ccw(c1780,2771.98) 1762.9,2725 ; 1730,2965 cw(c1780,2965) 1780,3015 1805,3015 ; 1730,3471.98 ccw(c1780,3471.98) 1762.9,3425 ; 1730,3665 cw(c1780,3665) 1780,3715 1805,3715 ; 1804.2,1969.19 ccw(c1854.2,1969.99) 1855,1920 ; 1804.2,2669.19 ccw(c1854.2,2669.99) 1855,2620 ; 1804.2,3369.19 ccw(c1854.2,3369.99) 1855,3320 ; 1849.01,2334.2 cw(c1899,2335) 1898.2,2384.99 ; 1849.01,3034.2 cw(c1899,3035) 1898.2,3084.99 ; 1849.01,3734.2 cw(c1899,3735) 1898.2,3784.99 ; 2022.41,1624.98 cw(c2020,1475) 2169.98,1472.59 ; 2124.95,3936.6 cw(c2208,3834) 2268.9,3716.89 ; 2199.2,2384.99 cw(c2200,2335) 2249.99,2335.8 ; 2199.2,3084.99 cw(c2200,3035) 2249.99,3035.8 ; 2199.2,3784.99 cw(c2200,3735) 2249.99,3735.8 ; 2200.8,1920.01 ccw(c2200,1970) 2249.99,1970.8 ; 2200.8,2620.01 ccw(c2200,2670) 2249.99,2670.8 ; 2200.8,3320.01 ccw(c2200,3370) 2249.99,3370.8 ; 2285,6947 cw(c2435,6947) 2360,7076.9 ; 2307.59,335.02 ccw(c2310,485) 2459.98,482.59 ; 2340.02,3332.41 ccw(c2490,3330) 2487.59,3180.02 ; 2375.01,1443.79 cw(c2450,1445) 2448.79,1519.99 ; 2460.02,7597.41 cw(c2610,7595) 2612.41,7744.98 ; 2544.2,1184.99 cw(c2545,1135) 2594.99,1135.8 ; 2595.01,118.79 ccw(c2670,120) 2671.21,45.01 ; 2633.02,3052.01 ccw(c2758,3050) 2755.99,2925.02 ; 2703.79,1519.99 cw(c2705,1445) 2779.99,1446.21 ; 2780.01,313.79 ccw(c2855,315) 2856.21,240.01 ; 2930.02,487.41 ccw(c3080,485) 3077.59,335.02 ; 2930.02,1477.41 cw(c3080,1475) 3082.41,1624.98 ; 2986.79,3315.99 cw(c2988,3241) 3062.99,3242.21 ; 3412.41,1624.98 cw(c3410,1475) 3559.98,1472.59 ; 3697.59,335.02 ccw(c3700,485) 3849.98,482.59 ; 3765.01,1443.79 cw(c3840,1445) 3838.79,1519.99 ; 3911.21,240.01 ccw(c3910,315) 3984.99,316.21 ; 3934.2,1184.99 cw(c3935,1135) 3984.99,1135.8 ; 4093.79,1519.99 cw(c4095,1445) 4169.99,1446.21 ; 4170.01,313.79 ccw(c4245,315) 4246.21,240.01 ; 4189,3265 cw(c4264,3265) 4238.35,3335.48 ; 4244.01,2925.02 ccw(c4242,3050) 4366.98,3052.01 ; 4320.02,487.41 ccw(c4470,485) 4467.59,335.02 ; 4320.02,1472.41 cw(c4470,1470) 4472.41,1619.98 ; 4514.85,3180 ccw(c4470,3296.67) 4594.98,3294.66 ; 4595.02,3842.01 cw(c4720,3840) 4722.01,3964.98 ; 4739.2,2325.81 cw(c4789.2,2325.01) 4790,2375 ; 4739.2,3025.81 cw(c4789.2,3025.01) 4790,3075 ; 4740,3725 cw(c4790,3725) 4790,3775 ; 4740.81,1820.8 ccw(c4790.8,1819.99) 4790,1770 ; 4740.81,2520.8 ccw(c4790.8,2519.99) 4790,2470 ; 4740.81,3220.8 ccw(c4790.8,3219.99) 4790,3170 ; 4802.41,1619.98 cw(c4800,1470) 4949.98,1467.59 ; 5087.59,335.02 ccw(c5090,485) 5239.98,482.59 ; 5155.01,1443.79 cw(c5230,1445) 5228.79,1519.99 ; 5220,1770 ccw(c5220.8,1819.99) 5270.8,1819.19 ; 5220,2375 cw(c5219.2,2325.01) 5269.19,2324.2 ; 5220,2470 ccw(c5220.8,2519.99) 5270.8,2519.19 ; 5220,3075 cw(c5219.2,3025.01) 5269.19,3024.2 ; 5220,3170 ccw(c5220.8,3219.99) 5270.8,3219.19 ; 5220,3775 cw(c5220,3725) 5270,3725 ; 5296.21,240.01 ccw(c5295,315) 5369.99,316.21 ; 5305,3965 ccw(c5307.01,4089.98) 5431.99,4087.97 ; 5320,1185 cw(c5320.8,1135.01) 5370.8,1135.81 ; 5420.01,1613.78 ccw(c5495,1614.99) 5496.21,1540 ; 5420.01,3693.79 cw(c5495,3695) 5493.79,3769.99 ; 5430.02,4517.57 cw(c5590,4515) 5592.57,4674.98 ; 5560.8,3770.01 ccw(c5560,3820) 5609.99,3820.8 ; 5610.01,3819.2 cw(c5660,3820) 5659.2,3869.99 ; 5724.41,7744.98 cw(c5722,7595) 5871.98,7592.59 ; 5730.01,378.79 ccw(c5805,380) 5806.21,305.01 ; 5730.01,423.79 cw(c5805,425) 5803.79,499.99 ; 5733.8,393.78 ccw(c5808.79,394.99) 5810,320 ; 5735.01,408.79 cw(c5810,410) 5808.79,484.99 ; 5747.59,4675.02 ccw(c5750,4825) 5899.98,4822.59 ; 5873.79,304.66 cw(c5875,229.67) 5949.99,230.88 ; 5873.79,1519.99 cw(c5875,1445) 5949.99,1446.21 ; 5873.79,3869.99 cw(c5875,3795) 5949.99,3796.21 ; 5876.21,45.01 ccw(c5875,120) 5949.99,121.21 ; 5876.21,500.01 ccw(c5875,575) 5949.99,576.21 ; 5888.79,319.99 cw(c5890,245) 5964.99,246.21 ; 5888.79,1539.99 cw(c5890,1465) 5964.99,1466.21 ; 5891.21,485.01 ccw(c5890,560) 5964.99,561.21 ; 5900.02,4922.59 cw(c6060,4920.02) 6062.57,5080 ; 5950.01,1973.79 ccw(c6025,1975) 6026.21,1900.01 ; 5965.01,118.79 ccw(c6040,120) 6041.21,45.01 ; 5965,2315 ccw(c6039.99,2316.21) 6041.2,2241.22 ; 5965.01,3693.79 cw(c6040,3695) 6038.79,3769.99 ; 6089.59,5080.02 ccw(c6092,5230) 6241.98,5227.59 ; 6097.41,7086.98 cw(c6095,6937) 6244.98,6934.59 ; 6331.21,3770.01 ccw(c6330,3845) 6404.99,3846.21 ; 6405.01,6103.79 cw(c6480,6105) 6478.79,6179.99 ; 6435.01,1983.79 ccw(c6510,1985) 6511.21,1910.01 ; 7019.2,879.19 ccw(c7069.2,879.99) 7070,830 ; 7020.01,919.2 cw(c7070,920) 7069.2,969.99 ; 7223.79,829.99 cw(c7225,755) 7299.99,756.21 ; 7226.21,970.01 ccw(c7225,1045) 7299.99,1046.21 ; 7300.01,628.79 ccw(c7375,630) 7376.21,555.01 ; 7300.01,1133.79 cw(c7375,1135) 7373.79,1209.99 ; 7435.01,4418.79 ccw(c7510,4420) 7511.21,4345.01 ; 7435.01,5608.79 cw(c7510,5610) 7508.79,5684.99 ; 7456.21,45.01 ccw(c7455,120) 7529.99,121.21 ; 7491.21,1910.01 ccw(c7490,1985) 7564.99,1986.21 ; 7506.21,1900.01 ccw(c7505,1975) 7579.99,1976.21 ; 7535.01,4686.79 ccw(c7610,4688) 7611.21,4613.01 ; 7535.01,5351.79 cw(c7610,5353) 7608.79,5427.99 ; 7565.01,2988.79 cw(c7640,2990) 7638.79,3064.99 ; 7580.01,2958.79 cw(c7655,2960) 7653.79,3034.99 ; 7633.8,4343.78 cw(c7635.01,4268.79) 7710,4270 ; 7710.01,3778.79 ccw(c7785,3780) 7786.21,3705.01 ; 7710.01,4491.12 ccw(c7765,4492) 7765.88,4437.01 ; 7715.01,5523.79 cw(c7790,5525) 7788.79,5599.99 ; 7726.22,3063.8 ccw(c7725.01,3138.79) 7800,3140 ; 7749.12,4439.99 cw(c7750,4385) 7804.99,4385.88 ; 7800.01,3128.79 cw(c7875,3130) 7873.79,3204.99 ; 7805.01,3889.2 ccw(c7855,3890) 7855.8,3840.01 ; 7821.21,3035.01 ccw(c7820,3110) 7894.99,3111.21 ; 7878.79,1209.99 cw(c7880,1135) 7954.99,1136.21 ; 7878.79,5599.99 cw(c7880,5525) 7954.99,5526.21 ; 7878.79,6179.99 cw(c7880,6105) 7954.99,6106.21 ; 7881.21,555.01 ccw(c7880,630) 7954.99,631.21 ; 7881.21,1210.01 ccw(c7880,1285) 7954.99,1286.21 ; 7881.21,3205.01 ccw(c7880,3280) 7954.99,3281.21 ; 7881.21,5685.01 ccw(c7880,5760) 7954.99,5761.21 ; 7883.79,3704.99 cw(c7885,3630) 7959.99,3631.21 ; 7895,3165 cw(c7920,3165.4) 7919.59,3190.4 ; 7904.2,554.99 cw(c7905,505) 7954.99,505.8 ; 7905.8,472.01 ccw(c7905,522) 7954.99,522.8 ; 7905.81,3839.2 ccw(c7905.01,3889.2) 7955,3890 ; 7929.6,3190 cw(c7930,3165) 7955,3165.4 ; 5580.01,4280.8 ccw(c5630,4279.99) 5629.2,4230 cw(c5630,4279.99) 5580.01,4280.8 ; 5580.01,4475.8 cw(c5630,4475) 5630.8,4524.99 ccw(c5630,4475) 5580.01,4475.8 ; 6000,4524.53 ccw(c6000.8,4574.52) 6050.8,4573.71 cw(c6000.8,4574.52) 6000,4524.53 ; 6050.01,4880.8 cw(c6100,4880) 6100.8,4929.99 ccw(c6100,4880) 6050.01,4880.8 ; 6249.2,4230.01 ccw(c6250,4280) 6299.99,4279.2 cw(c6250,4280) 6249.2,4230.01 ; 6250.8,4929.99 cw(c6250,4880) 6299.99,4879.2 ccw(c6250,4880) 6250.8,4929.99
